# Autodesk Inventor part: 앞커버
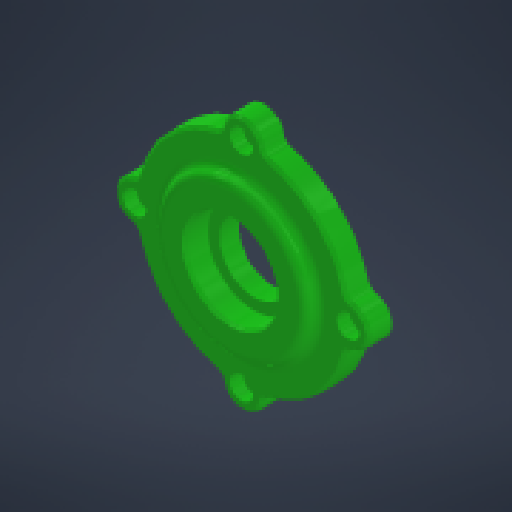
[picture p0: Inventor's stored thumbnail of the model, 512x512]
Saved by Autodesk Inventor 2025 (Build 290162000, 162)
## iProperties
Created: 2025-08
Part Number: 앞커버
Material: 알루미늄 6061
Document SubType Name: Modeling
Designer: infra023
Density: 2.71 g/cm^3
Appearance: 기본값
Company: 한국ATC센터
Author: jhkim
Sending System: Autodesk Inventor 2026
Preprocessor: ST-DEVELOPER v20.1
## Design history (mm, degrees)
feature "솔리드1"
node "솔리드2"
